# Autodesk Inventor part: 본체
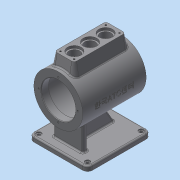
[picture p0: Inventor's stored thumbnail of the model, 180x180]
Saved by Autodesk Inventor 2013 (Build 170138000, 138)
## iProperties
Created: 2015-11
Part Number: 본체
Material: 알루미늄 6061
Document SubType Name: Modeling
Designer: mduedu
Density: 2.71 g/cm^3
Mass: 1557.05 g
Surface Area: 1415.52 cm^2
Volume: 574.557 cm^3
Author: mduedu
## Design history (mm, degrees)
sketch "스케치2"
  geometry: C1 r 50 at (0, 0); 1 further point
  constraints: 1 centre point, 1 coincident
  dimensions: "d147" = 100 diameter of C1
extrude "돌출1" new body sketch "스케치2" stored distance "d12" = 130; taper "d13" = 0 deg
feature "쉘1" dims "d31" = 15, "d32" = 6, "d33" = 15
sketch "스케치5"
  geometry: C1 r 35 at (0, 0); 1 further point
  constraints: 1 centre point, 1 coincident
  dimensions: "d34" = 70 diameter of C1
extrude "돌출3" cut sketch "스케치5" stored distance "d36" = 3; taper "d37" = 0 deg
node "작업 평면1"
sketch "스케치6"
  geometry: L1 (-65, -60)-(65, -60); L2 (65, -60)-(65, 60); L3 (65, 60)-(-65, 60); L4 (-65, 60)-(-65, -60); L5 (-65, -60)-(65, 60); L6 (65, -60)-(-65, 60); 1 further point
  constraints: 12 end point, 2 midpoint, 2 parallel, 1 horizontal, 1 perpendicular
  dimensions: "d41" = 120 distance of L3.end L1.start; "d43" = 130 distance of L2.end L3.end
extrude "돌출4" join sketch "스케치6" distance "d44" = 10; taper "d45" = 0 deg
sketch "스케치19"
  geometry: L1 (-45, 30)-(-35, 30); L2 (-35, 30)-(-35, -30); L3 (-35, -30)-(-45, -30); L4 (-45, -30)-(-45, 30); L5 (-65, 60)-(-65, -60) reference; 2 further points
  constraints: 8 end point, 2 parallel, 1 horizontal, 1 horizontal alignment, 1 midpoint, 1 perpendicular
  dimensions: "d150" = 20 distance between parallel lines of L4 L5; "d151" = 10 distance of L1.start L1.end; "d152" = 60 distance of L3.end L1.start
extrude "돌출9" join sketch "스케치19" stored distance "d153" = 10; taper "d154" = 0 deg
sketch "스케치20"
  geometry: L1 (65, 35)-(50, 35) reference; L2 (50, 35)-(50, 44) reference; L3 (50, 44)-(-50, 44) reference; L4 (-50, 44)-(-50, 35) reference; L5 (-50, 35)-(-65, 35) reference; L6 (-65, 35)-(-65, 50) reference; L7 (-65, 50)-(65, 50) reference; L8 (65, 50)-(65, 35) reference; L9 (50, -35)-(65, -35) reference; L10 (65, -35)-(65, -50) reference; L11 (65, -50)-(45, -50) reference; L12 (45, -50)-(45, -90) reference; L13 (45, -90)-(65, -90) reference; L14 (65, -90)-(65, -100) reference; L15 (65, -100)-(-65, -100) reference; L16 (-65, -100)-(-65, -90) reference; L17 (-65, -90)-(35, -90) reference; L18 (35, -90)-(35, -50) reference; L19 (35, -50)-(-65, -50) reference; L20 (-65, -50)-(-65, -35) reference; L21 (-65, -35)-(-50, -35) reference; L22 (-50, -35)-(-50, -44) reference; L23 (-50, -44)-(50, -44) reference; L24 (50, -44)-(50, -35) reference; L25 (-45, -90)-(-21.906, -50); 1 further point
  constraints: 2 end point, 2 point on line
  dimensions: "d155" = 20 distance from line of L25.start L16; "d156" = 120 deg angle of L25 L17
feature "리브2" sketch "스케치20" dims "d157" = 1, "d158" = 10, "d159" = 0, "d160" = 0, "d161" = 1, "d162" = 1
fillet "모깎기21" dims "d163" = 3
fillet "모깎기22" dims "d164" = 3
fillet "모깎기23" dims "d165" = 3
sketch "스케치21" dims "d166" = 80
  geometry: 3 further points
  constraints: 2 horizontal alignment, 1 coincident, 2 other
hole "구멍6" sketch "스케치21" at (40, 0) diameter "d168" = 3.242; stored, may be unused: countersink angle "d172" = 90 deg, drill point angle "d174" = 118 deg; dims "d169" = 9, "d170" = 4, "d171" = 2, "d173" = 11
node "작업 평면2"
sketch "스케치13"
  geometry: L1 (-52.5, -20)-(52.5, -20); L2 (52.5, -20)-(52.5, 20); L3 (52.5, 20)-(-52.5, 20); L4 (-52.5, 20)-(-52.5, -20); L5 (-52.5, -20)-(52.5, 20); L6 (52.5, -20)-(-52.5, 20); 1 further point
  constraints: 12 end point, 2 midpoint, 2 parallel, 1 horizontal, 1 perpendicular
  dimensions: "d93" = 105 distance of L2.end L3.end; "d95" = 40 distance of L1.end L2.end
extrude "돌출8" join sketch "스케치13" stored distance "d96" = 80; taper "d97" = 0 deg
fillet "모깎기15" dims "d98" = 5
feature "면 기울기1" dims angle "d178" = 10 deg
fillet "모깎기24" dims "d179" = 3
sketch "스케치14"
  geometry: L1 (-52.5, 15)-(-52.5, -15) reference; L2 (52.5, -15)-(52.5, 15) reference; L3 (-52.5, 0)-(52.5, 0); 4 further points
  constraints: 2 end point, 2 midpoint, 2 point on line, 1 coincident
  dimensions: "d100" = 32 distance of point (-32, 0) point (0, 0); "d102" = 32 distance of point (32, 0) point (0, 0) (derived)
hole "구멍3" sketch "스케치14" at (-32, 0), (0, 0), (32, 0) diameter "d103" = 22; stored, may be unused: countersink angle "d107" = 90 deg, drill point angle "d109" = 118 deg; dims "d104" = 8, "d105" = 28, "d106" = 5, "d108" = 10
sketch "스케치15"
  geometry: L1 (46.5, -14)-(-46.5, -14); L2 (-46.5, -14)-(-46.5, 14); L3 (-46.5, 14)-(46.5, 14); L4 (46.5, 14)-(46.5, -14); L5 (46.5, -14)-(-46.5, 14); L6 (-46.5, -14)-(46.5, 14); L7 (47.5, 20)-(-47.5, 20) reference; L8 (-52.5, 15)-(-52.5, -15) reference; 5 further points
  constraints: 12 end point, 4 coincident, 2 midpoint, 2 parallel, 1 horizontal, 1 perpendicular
  dimensions: "d110" = 6 distance between parallel lines of L3 L7; "d111" = 6 distance between parallel lines of L2 L8
hole "구멍4" sketch "스케치15" at (-46.5, 14), (46.5, 14), (46.5, -14), (-46.5, -14) diameter "d112" = 3.242; stored, may be unused: countersink angle "d116" = 90 deg, drill point angle "d118" = 118 deg; dims "d113" = 10, "d114" = 28, "d115" = 5, "d117" = 13
node "작업 평면3"
sketch "스케치22"
  geometry: 2 further points
  constraints: 1 coincident, 1 other
feature "엠보싱3" sketch "스케치22" dims "d32" = 6, "d181" = 0.5, "d182" = 0
chamfer "모따기2" distance "d183" = 1; stored, may be unused: second distance "d184" = 2, angle "d185" = 45 deg
fillet "모깎기25" dims "d186" = 10
sketch "스케치23"
  geometry: L1 (55, 60)-(-55, 60) reference; L2 (65, -50)-(65, 50) reference; L3 (-55, -60)-(55, -60) reference; L4 (-65, 50)-(-65, -50) reference; A1 r 10 centre (-55, 50) between (-55, 60) and (-65, 50) reference; A2 r 10 centre (55, 50) between (65, 50) and (55, 60) reference; A3 r 10 centre (55, -50) between (55, -60) and (65, -50) reference; A4 r 10 centre (-55, -50) between (-65, -50) and (-55, -60) reference; 1 further point
hole "구멍7" sketch "스케치23" at (-55, 50), (-55, -50), (55, -50), (55, 50) diameter "d187" = 6; stored, may be unused: countersink angle "d191" = 90 deg, drill point angle "d193" = 118 deg; dims "d188" = 9, "d189" = 10, "d190" = 2, "d192" = 11
fillet "모깎기26" dims "d194" = 3
node "솔리드1"
pattern_circular "원형 패턴2" dims angle "d176" = 360 deg
mirror "대칭5"
node "투영된 루프2"
node "절단 모서리 투영1"
